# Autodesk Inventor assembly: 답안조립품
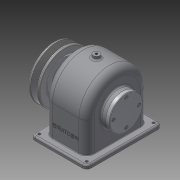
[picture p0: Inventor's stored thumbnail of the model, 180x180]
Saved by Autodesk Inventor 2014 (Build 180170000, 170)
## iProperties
Created: 2016-01
Part Number: 답안조립품
Document SubType Name: Assembly
Designer: USER
Author: USER
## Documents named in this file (16)
- C:\Users\USER\Desktop\460105V1024\답안조립품.iam
- C:\Users\USER\Desktop\460105V1024\본체.ipt
- C:\Users\USER\Desktop\460105V1024\V-벨트풀리.ipt
- C:\Users\USER\Desktop\460105V1024\뒤커버.ipt
- C:\Users\USER\Desktop\460105V1024\멈춤나사 - M4x10.ipt
- C:\Users\USER\Desktop\460105V1024\베어링 6203.ipt
- C:\Users\USER\Desktop\460105V1024\볼트 M3 x 8.ipt
- C:\Users\USER\Desktop\460105V1024\볼트 M3 x 10.ipt
- C:\Users\USER\Desktop\460105V1024\부시1.ipt
- C:\Users\USER\Desktop\460105V1024\부시2.ipt
- C:\Users\USER\Desktop\460105V1024\스퍼기어.ipt
- C:\Users\USER\Desktop\460105V1024\앞커버.ipt
- C:\Users\USER\Desktop\460105V1024\오일씰 28 40 8.ipt
- C:\Users\USER\Desktop\460105V1024\축.ipt
- C:\Users\USER\Desktop\460105V1024\키 - 5 x 5 x 18.ipt
- C:\Users\USER\Desktop\460105V1024\키 - 6 x 6 x 22.ipt
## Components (9 placed, 3 different names)
1. V-벨트풀리:1
2. ISO 4762 M3 x 8:2
3. ISO 4762 M3 x 8:3
4. ISO 4762 M3 x 8:4
5. ISO 4762 M3 x 8:5
6. ISO 4762 M3 x 10:2
7. ISO 4762 M3 x 10:3
8. ISO 4762 M3 x 10:4
9. ISO 4762 M3 x 10:5
